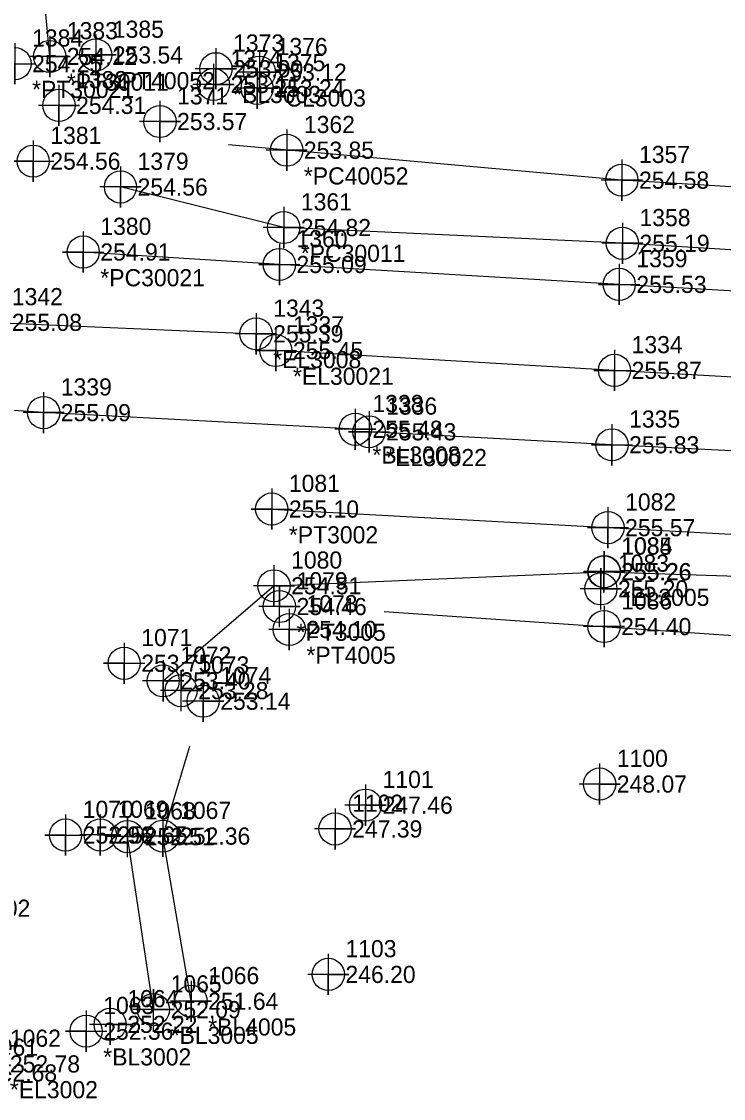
# Model space of a CAD drawing. Extents: x 2130962 to 2131465, y 643052 to 644206.
# Drawn here: x 2131260.2 to 2131362.5, y 643070.6 to 643227.7 of the extents above; entities that cross this region are included whole.
import ezdxf

# ---------------------------------------------------------------- set-up
doc = ezdxf.new("R2010")
doc.units = 0
for name, color, linetype in [('Exist DTM Breakline', 7, 'Continuous'), ('Exist DTM Breakline Cogo Comment', 7, 'Continuous'), ('Exist DTM Breakline Cogo Elevation', 7, 'Continuous'), ('Exist DTM Breakline Cogo Number', 7, 'Continuous'), ('Exist DTM Breakline Cogo Point CELL', 7, 'Continuous'), ('Exist DTM Crownline', 7, 'Continuous'), ('Exist DTM Crownline Cogo Comment', 7, 'Continuous'), ('Exist DTM Crownline Cogo Elevation', 7, 'Continuous'), ('Exist DTM Crownline Cogo Number', 7, 'Continuous'), ('Exist DTM Crownline Cogo Point CELL', 7, 'Continuous'), ('Exist DTM Regular Point CELL', 7, 'Continuous'), ('Exist DTM Regular Point Cogo Elevation', 7, 'Continuous'), ('Exist DTM Regular Point Cogo Number', 7, 'Continuous'), ('Exist Roads EOP', 7, 'Continuous'), ('Exist Roads EOP Cogo Comment', 7, 'Continuous'), ('Exist Roads EOP Cogo Elevation', 7, 'Continuous'), ('Exist Roads EOP Cogo Number', 7, 'Continuous'), ('Exist Roads EOP Cogo Point CELL', 7, 'Continuous'), ('Exist Roads EOP Other Cogo Comment', 7, 'Continuous'), ('Exist Roads EOP Other Cogo Elevation', 7, 'Continuous'), ('Exist Roads EOP Other Cogo Number', 7, 'Continuous'), ('Exist Roads EOP Other Cogo Point CELL', 7, 'Continuous'), ('Exist Roads EOT', 7, 'Continuous'), ('Exist Roads EOT Cogo Comment', 7, 'Continuous'), ('Exist Roads EOT Cogo Elevation', 7, 'Continuous'), ('Exist Roads EOT Cogo Number', 7, 'Continuous'), ('Exist Roads EOT Cogo Point CELL', 7, 'Continuous'), ('Exist Roads Soil', 7, 'Continuous'), ('Exist Roads Soil Cogo Comment', 7, 'Continuous'), ('Exist Roads Soil Cogo Elevation', 7, 'Continuous'), ('Exist Roads Soil Cogo Number', 7, 'Continuous'), ('Exist Roads Soil Cogo Point CELL', 7, 'Continuous')]:
    doc.layers.add(name, color=color, linetype=linetype)

msp = doc.modelspace()

# ---------------------------------------------------------------- linework, layer by layer
at = {"layer": 'Exist DTM Breakline'}
msp.add_line((2131313.0171, 643141.6555), (2131395.8335, 643135.9257), dxfattribs=at)
for points in [[(2131447.7276, 643199.0466), (2131397.0228, 643201.4878), (2131347.6587, 643204.5248), (2131290.3074, 643209.6518)], [(2131284.8719, 643084.8081), (2131280.7793, 643108.8884), (2131284.6857, 643122.0133)]]:
    msp.add_lwpolyline(points, dxfattribs=at)
at = {"layer": 'Exist DTM Breakline Cogo Point CELL'}
for points in [[(2131270.9763, 643225.7805), (2131270.9763, 643219.7805), (2131270.9763, 643222.7805), (2131273.9763, 643222.7805), (2131267.9763, 643222.7805)], [(2131280.339, 643216.0688), (2131280.339, 643210.0688), (2131280.339, 643213.0688), (2131283.339, 643213.0688), (2131277.339, 643213.0688)], [(2131298.816, 643211.8912), (2131298.816, 643205.8912), (2131298.816, 643208.8912), (2131301.816, 643208.8912), (2131295.816, 643208.8912)], [(2131347.6587, 643207.5248), (2131347.6587, 643201.5248), (2131347.6587, 643204.5248), (2131350.6587, 643204.5248), (2131344.6587, 643204.5248)], [(2131299.1949, 643142.0122), (2131299.1949, 643136.0122), (2131299.1949, 643139.0122), (2131302.1949, 643139.0122), (2131296.1949, 643139.0122)], [(2131345.0539, 643142.439), (2131345.0539, 643136.439), (2131345.0539, 643139.439), (2131348.0539, 643139.439), (2131342.0539, 643139.439)], [(2131286.6315, 643131.5508), (2131286.6315, 643125.5508), (2131286.6315, 643128.5508), (2131289.6315, 643128.5508), (2131283.6315, 643128.5508)], [(2131280.7793, 643111.8884), (2131280.7793, 643105.8884), (2131280.7793, 643108.8884), (2131283.7793, 643108.8884), (2131277.7793, 643108.8884)], [(2131284.8719, 643087.8081), (2131284.8719, 643081.8081), (2131284.8719, 643084.8081), (2131287.8719, 643084.8081), (2131281.8719, 643084.8081)]]:
    msp.add_lwpolyline(points, dxfattribs=at)
for centre in [(2131270.9763, 643222.7805), (2131280.339, 643213.0688), (2131298.816, 643208.8912), (2131347.6587, 643204.5248), (2131345.0539, 643139.439), (2131299.1949, 643139.0122), (2131286.6315, 643128.5508), (2131280.7793, 643108.8884), (2131284.8719, 643084.8081)]:
    msp.add_circle(centre, 2.344, dxfattribs=at)
at = {"layer": 'Exist DTM Crownline'}
for points in [[(2131228.6932, 643183.6314), (2131256.2577, 643183.7922), (2131294.3471, 643182.1169)], [(2131308.8055, 643168.2032), (2131263.3929, 643170.6252), (2131227.5461, 643173.0169)]]:
    msp.add_lwpolyline(points, dxfattribs=at)
at = {"layer": 'Exist DTM Crownline Cogo Point CELL'}
for points in [[(2131294.3471, 643185.1169), (2131294.3471, 643179.1169), (2131294.3471, 643182.1169), (2131297.3471, 643182.1169), (2131291.3471, 643182.1169)], [(2131263.3929, 643173.6252), (2131263.3929, 643167.6252), (2131263.3929, 643170.6252), (2131266.3929, 643170.6252), (2131260.3929, 643170.6252)], [(2131308.8055, 643171.2032), (2131308.8055, 643165.2032), (2131308.8055, 643168.2032), (2131311.8055, 643168.2032), (2131305.8055, 643168.2032)]]:
    msp.add_lwpolyline(points, dxfattribs=at)
for centre in [(2131294.3471, 643182.1169), (2131263.3929, 643170.6252), (2131308.8055, 643168.2032)]:
    msp.add_circle(centre, 2.344, dxfattribs=at)
at = {"layer": 'Exist DTM Regular Point CELL'}
for points in [[(2131344.4182, 643119.4774), (2131344.4182, 643113.4774), (2131344.4182, 643116.4774), (2131347.4182, 643116.4774), (2131341.4182, 643116.4774)], [(2131310.2902, 643116.4027), (2131310.2902, 643110.4027), (2131310.2902, 643113.4027), (2131313.2902, 643113.4027), (2131307.2902, 643113.4027)], [(2131305.8527, 643112.9315), (2131305.8527, 643106.9315), (2131305.8527, 643109.9315), (2131308.8527, 643109.9315), (2131302.8527, 643109.9315)], [(2131304.8747, 643091.7233), (2131304.8747, 643085.7233), (2131304.8747, 643088.7233), (2131307.8747, 643088.7233), (2131301.8747, 643088.7233)]]:
    msp.add_lwpolyline(points, dxfattribs=at)
for centre in [(2131344.4182, 643116.4774), (2131310.2902, 643113.4027), (2131305.8527, 643109.9315), (2131304.8747, 643088.7233)]:
    msp.add_circle(centre, 2.344, dxfattribs=at)
at = {"layer": 'Exist Roads EOP'}
for points in [[(2131264.2715, 643222.5647), (2131259.8757, 643269.3254), (2131257.0196, 643319.4043), (2131254.2561, 643369.6499), (2131250.0777, 643419.4187), (2131246.1511, 643469.0294), (2131240.8382, 643519.1271), (2131234.3674, 643568.5584), (2131226.3321, 643620.1808), (2131217.0271, 643668.7116), (2131205.6213, 643717.607), (2131192.0578, 643767.2595), (2131177.9714, 643815.0911), (2131162.2913, 643862.9344), (2131145.3604, 643910.8486), (2131126.9113, 643957.2915), (2131112.3691, 643996.1228)], [(2131447.2378, 643189.5276), (2131397.3957, 643192.2966), (2131347.7242, 643195.3218), (2131298.3748, 643197.6139), (2131274.5841, 643203.5275)], [(2131280.8132, 643131.5166), (2131296.9579, 643145.3867), (2131345.0473, 643147.4189), (2131395.7747, 643145.7863), (2131444.2123, 643144.2465)]]:
    msp.add_lwpolyline(points, dxfattribs=at)
at = {"layer": 'Exist Roads EOP Cogo Point CELL'}
for points in [[(2131264.2715, 643225.5647), (2131264.2715, 643219.5647), (2131264.2715, 643222.5647), (2131267.2715, 643222.5647), (2131261.2715, 643222.5647)], [(2131265.6198, 643218.4271), (2131265.6198, 643212.4271), (2131265.6198, 643215.4271), (2131268.6198, 643215.4271), (2131262.6198, 643215.4271)], [(2131274.5841, 643206.5275), (2131274.5841, 643200.5275), (2131274.5841, 643203.5275), (2131277.5841, 643203.5275), (2131271.5841, 643203.5275)], [(2131298.3748, 643200.6139), (2131298.3748, 643194.6139), (2131298.3748, 643197.6139), (2131301.3748, 643197.6139), (2131295.3748, 643197.6139)], [(2131347.7242, 643198.3218), (2131347.7242, 643192.3218), (2131347.7242, 643195.3218), (2131350.7242, 643195.3218), (2131344.7242, 643195.3218)], [(2131345.0473, 643150.4189), (2131345.0473, 643144.4189), (2131345.0473, 643147.4189), (2131348.0473, 643147.4189), (2131342.0473, 643147.4189)], [(2131296.9579, 643148.3867), (2131296.9579, 643142.3867), (2131296.9579, 643145.3867), (2131299.9579, 643145.3867), (2131293.9579, 643145.3867)], [(2131280.8132, 643134.5166), (2131280.8132, 643128.5166), (2131280.8132, 643131.5166), (2131283.8132, 643131.5166), (2131277.8132, 643131.5166)], [(2131271.6455, 643112.0511), (2131271.6455, 643106.0511), (2131271.6455, 643109.0511), (2131274.6455, 643109.0511), (2131268.6455, 643109.0511)], [(2131273.0839, 643084.4429), (2131273.0839, 643078.4429), (2131273.0839, 643081.4429), (2131276.0839, 643081.4429), (2131270.0839, 643081.4429)]]:
    msp.add_lwpolyline(points, dxfattribs=at)
for centre in [(2131264.2715, 643222.5647), (2131265.6198, 643215.4271), (2131274.5841, 643203.5275), (2131298.3748, 643197.6139), (2131347.7242, 643195.3218), (2131345.0473, 643147.4189), (2131296.9579, 643145.3867), (2131280.8132, 643131.5166), (2131271.6455, 643109.0511), (2131273.0839, 643081.4429)]:
    msp.add_circle(centre, 2.344, dxfattribs=at)
at = {"layer": 'Exist Roads EOP Other Cogo Point CELL'}
for points in [[(2131288.4961, 643223.7686), (2131288.4961, 643217.7686), (2131288.4961, 643220.7686), (2131291.4961, 643220.7686), (2131285.4961, 643220.7686)], [(2131294.8401, 643223.2582), (2131294.8401, 643217.2582), (2131294.8401, 643220.2582), (2131297.8401, 643220.2582), (2131291.8401, 643220.2582)], [(2131288.1379, 643221.4835), (2131288.1379, 643215.4835), (2131288.1379, 643218.4835), (2131291.1379, 643218.4835), (2131285.1379, 643218.4835)], [(2131294.5029, 643220.9136), (2131294.5029, 643214.9136), (2131294.5029, 643217.9136), (2131297.5029, 643217.9136), (2131291.5029, 643217.9136)]]:
    msp.add_lwpolyline(points, dxfattribs=at)
for centre in [(2131288.4961, 643220.7686), (2131294.8401, 643220.2582), (2131288.1379, 643218.4835), (2131294.5029, 643217.9136)]:
    msp.add_circle(centre, 2.344, dxfattribs=at)
at = {"layer": 'Exist Roads EOT'}
for points in [[(2131447.0543, 643183.628), (2131397.23, 643186.4537), (2131347.2728, 643189.3277), (2131297.7395, 643192.2318), (2131269.1537, 643194.0491)], [(2131446.3277, 643171.1555), (2131396.6439, 643173.9458), (2131346.5769, 643176.7932), (2131297.2277, 643179.6845)], [(2131445.8347, 643160.7067), (2131396.5039, 643163.4177), (2131346.2151, 643165.9442), (2131310.8065, 643167.8349)], [(2131296.63, 643156.5688), (2131345.6305, 643153.8593), (2131395.87, 643151.1658)]]:
    msp.add_lwpolyline(points, dxfattribs=at)
at = {"layer": 'Exist Roads EOT Cogo Point CELL'}
for points in [[(2131259.2129, 643224.5063), (2131259.2129, 643218.5063), (2131259.2129, 643221.5063), (2131256.2129, 643221.5063), (2131262.2129, 643221.5063)], [(2131261.865, 643210.302), (2131261.865, 643204.302), (2131261.865, 643207.302), (2131258.865, 643207.302), (2131264.865, 643207.302)], [(2131269.1537, 643197.0491), (2131269.1537, 643191.0491), (2131269.1537, 643194.0491), (2131266.1537, 643194.0491), (2131272.1537, 643194.0491)], [(2131297.7395, 643195.2318), (2131297.7395, 643189.2318), (2131297.7395, 643192.2318), (2131294.7395, 643192.2318), (2131300.7395, 643192.2318)], [(2131347.2728, 643192.3277), (2131347.2728, 643186.3277), (2131347.2728, 643189.3277), (2131344.2728, 643189.3277), (2131350.2728, 643189.3277)], [(2131297.2277, 643182.6845), (2131297.2277, 643176.6845), (2131297.2277, 643179.6845), (2131294.2277, 643179.6845), (2131300.2277, 643179.6845)], [(2131346.5769, 643179.7932), (2131346.5769, 643173.7932), (2131346.5769, 643176.7932), (2131343.5769, 643176.7932), (2131349.5769, 643176.7932)], [(2131310.8065, 643170.8349), (2131310.8065, 643164.8349), (2131310.8065, 643167.8349), (2131307.8065, 643167.8349), (2131313.8065, 643167.8349)], [(2131346.2151, 643168.9442), (2131346.2151, 643162.9442), (2131346.2151, 643165.9442), (2131343.2151, 643165.9442), (2131349.2151, 643165.9442)], [(2131296.63, 643159.5688), (2131296.63, 643153.5688), (2131296.63, 643156.5688), (2131293.63, 643156.5688), (2131299.63, 643156.5688)], [(2131345.6305, 643156.8593), (2131345.6305, 643150.8593), (2131345.6305, 643153.8593), (2131342.6305, 643153.8593), (2131348.6305, 643153.8593)], [(2131275.1215, 643137.0881), (2131275.1215, 643131.0881), (2131275.1215, 643134.0881), (2131272.1215, 643134.0881), (2131278.1215, 643134.0881)], [(2131266.5862, 643112.0425), (2131266.5862, 643106.0425), (2131266.5862, 643109.0425), (2131263.5862, 643109.0425), (2131269.5862, 643109.0425)], [(2131269.5812, 643083.4443), (2131269.5812, 643077.4443), (2131269.5812, 643080.4443), (2131266.5812, 643080.4443), (2131272.5812, 643080.4443)]]:
    msp.add_lwpolyline(points, dxfattribs=at)
for centre in [(2131259.2129, 643221.5063), (2131261.865, 643207.302), (2131269.1537, 643194.0491), (2131297.7395, 643192.2318), (2131347.2728, 643189.3277), (2131297.2277, 643179.6845), (2131346.5769, 643176.7932), (2131310.8065, 643167.8349), (2131346.2151, 643165.9442), (2131296.63, 643156.5688), (2131345.6305, 643153.8593), (2131275.1215, 643134.0881), (2131266.5862, 643109.0425), (2131269.5812, 643080.4443)]:
    msp.add_circle(centre, 2.344, dxfattribs=at)
at = {"layer": 'Exist Roads Soil'}
msp.add_lwpolyline([(2131279.3978, 643083.5901), (2131275.6146, 643108.8098)], dxfattribs=at)
at = {"layer": 'Exist Roads Soil Cogo Point CELL'}
for points in [[(2131345.0899, 643144.45), (2131345.0899, 643150.45), (2131345.0899, 643147.45), (2131348.0899, 643147.45), (2131342.0899, 643147.45)], [(2131344.5951, 643141.934), (2131344.5951, 643147.934), (2131344.5951, 643144.934), (2131347.5951, 643144.934), (2131341.5951, 643144.934)], [(2131297.7505, 643139.3596), (2131297.7505, 643145.3596), (2131297.7505, 643142.3596), (2131300.7505, 643142.3596), (2131294.7505, 643142.3596)], [(2131283.4229, 643127.0933), (2131283.4229, 643133.0933), (2131283.4229, 643130.0933), (2131286.4229, 643130.0933), (2131280.4229, 643130.0933)], [(2131275.6146, 643105.8098), (2131275.6146, 643111.8098), (2131275.6146, 643108.8098), (2131278.6146, 643108.8098), (2131272.6146, 643108.8098)], [(2131279.3978, 643080.5901), (2131279.3978, 643086.5901), (2131279.3978, 643083.5901), (2131282.3978, 643083.5901), (2131276.3978, 643083.5901)]]:
    msp.add_lwpolyline(points, dxfattribs=at)
for centre in [(2131345.0899, 643147.45), (2131344.5951, 643144.934), (2131297.7505, 643142.3596), (2131283.4229, 643130.0933), (2131275.6146, 643108.8098), (2131279.3978, 643083.5901)]:
    msp.add_circle(centre, 2.344, dxfattribs=at)

# ---------------------------------------------------------------- texts
at = {"layer": 'Exist DTM Breakline Cogo Comment'}
for s, p in [('*PT40052', (2131273.4763, 643217.7805)), ('*PC40052', (2131301.316, 643203.8912)), ('*PT4005', (2131301.6949, 643134.0122)), ('*BL4005', (2131287.3719, 643079.8081))]:
    msp.add_text(s, height=2.5, dxfattribs=at).set_placement(p)
at = {"layer": 'Exist DTM Breakline Cogo Elevation'}
for s, p in [('253.54', (2131273.4763, 643221.5305)), ('253.57', (2131282.839, 643211.8188)), ('253.85', (2131301.316, 643207.6412)), ('254.58', (2131350.1587, 643203.2748)), ('254.10', (2131301.6949, 643137.7622)), ('254.40', (2131347.5539, 643138.189)), ('253.14', (2131289.1315, 643127.3008)), ('252.36', (2131283.2793, 643107.6384)), ('251.64', (2131287.3719, 643083.5581))]:
    msp.add_text(s, height=2.5, dxfattribs=at).set_placement(p)
at = {"layer": 'Exist DTM Breakline Cogo Number'}
for s, p in [('1385', (2131273.4763, 643225.2805)), ('1371', (2131282.839, 643215.5688)), ('1362', (2131301.316, 643211.3912)), ('1357', (2131350.1587, 643207.0248)), ('1078', (2131301.6949, 643141.5122)), ('1086', (2131347.5539, 643141.939)), ('1074', (2131289.1315, 643131.0508)), ('1067', (2131283.2793, 643111.3884)), ('1066', (2131287.3719, 643087.3081))]:
    msp.add_text(s, height=2.5, dxfattribs=at).set_placement(p)
at = {"layer": 'Exist DTM Crownline Cogo Comment'}
for s, p in [('*EL3008', (2131296.8471, 643177.1169)), ('*BL3008', (2131311.3055, 643163.2032))]:
    msp.add_text(s, height=2.5, dxfattribs=at).set_placement(p)
at = {"layer": 'Exist DTM Crownline Cogo Elevation'}
for s, p in [('255.08', (2131258.7577, 643182.5422)), ('255.39', (2131296.8471, 643180.8669)), ('255.09', (2131265.8929, 643169.3752)), ('255.48', (2131311.3055, 643166.9532))]:
    msp.add_text(s, height=2.5, dxfattribs=at).set_placement(p)
at = {"layer": 'Exist DTM Crownline Cogo Number'}
for s, p in [('1342', (2131258.7577, 643186.2922)), ('1343', (2131296.8471, 643184.6169)), ('1339', (2131265.8929, 643173.1252)), ('1338', (2131311.3055, 643170.7032))]:
    msp.add_text(s, height=2.5, dxfattribs=at).set_placement(p)
at = {"layer": 'Exist DTM Regular Point Cogo Elevation'}
for s, p in [('248.07', (2131346.9182, 643115.2274)), ('247.46', (2131312.7902, 643112.1527)), ('247.39', (2131308.3527, 643108.6815)), ('246.20', (2131307.3747, 643087.4733))]:
    msp.add_text(s, height=2.5, dxfattribs=at).set_placement(p)
at = {"layer": 'Exist DTM Regular Point Cogo Number'}
for s, p in [('1100', (2131346.9182, 643118.9774)), ('1101', (2131312.7902, 643115.9027)), ('1102', (2131308.3527, 643112.4315)), ('1103', (2131307.3747, 643091.2233))]:
    msp.add_text(s, height=2.5, dxfattribs=at).set_placement(p)
at = {"layer": 'Exist Roads EOP Cogo Comment'}
for s, p in [('*PT30011', (2131266.7715, 643217.5647)), ('*PC30011', (2131300.8748, 643192.6139))]:
    msp.add_text(s, height=2.5, dxfattribs=at).set_placement(p)
at = {"layer": 'Exist Roads EOP Cogo Elevation'}
for s, p in [('254.12', (2131266.7715, 643221.3147)), ('254.31', (2131268.1198, 643214.1771)), ('254.56', (2131277.0841, 643202.2775)), ('254.82', (2131300.8748, 643196.3639)), ('255.19', (2131350.2242, 643194.0718)), ('255.26', (2131347.5473, 643146.1689)), ('254.51', (2131299.4579, 643144.1367)), ('253.40', (2131283.3132, 643130.2666)), ('252.65', (2131274.1455, 643107.8011)), ('252.22', (2131275.5839, 643080.1929)), ('252.68', (2131255.1325, 643073.1047))]:
    msp.add_text(s, height=2.5, dxfattribs=at).set_placement(p)
at = {"layer": 'Exist Roads EOP Cogo Number'}
for s, p in [('1383', (2131266.7715, 643225.0647)), ('1382', (2131268.1198, 643217.9271)), ('1379', (2131277.0841, 643206.0275)), ('1361', (2131300.8748, 643200.1139)), ('1358', (2131350.2242, 643197.8218)), ('1085', (2131347.5473, 643149.9189)), ('1080', (2131299.4579, 643147.8867)), ('1072', (2131283.3132, 643134.0166)), ('1069', (2131274.1455, 643111.5511)), ('1064', (2131275.5839, 643083.9429)), ('1061', (2131255.1325, 643076.8547))]:
    msp.add_text(s, height=2.5, dxfattribs=at).set_placement(p)
at = {"layer": 'Exist Roads EOP Other Cogo Comment'}
for s, p in [('*BL3003', (2131290.9961, 643215.7686)), ('*CL3003', (2131297.3401, 643215.2582))]:
    msp.add_text(s, height=2.5, dxfattribs=at).set_placement(p)
at = {"layer": 'Exist Roads EOP Other Cogo Elevation'}
for s, p in [('253.00', (2131290.9961, 643219.5186)), ('253.12', (2131297.3401, 643219.0082)), ('253.11', (2131290.6379, 643217.2335)), ('253.24', (2131297.0029, 643216.6636))]:
    msp.add_text(s, height=2.5, dxfattribs=at).set_placement(p)
at = {"layer": 'Exist Roads EOP Other Cogo Number'}
for s, p in [('1373', (2131290.9961, 643223.2686)), ('1376', (2131297.3401, 643222.7582)), ('1374', (2131290.6379, 643220.9835)), ('1375', (2131297.0029, 643220.4136))]:
    msp.add_text(s, height=2.5, dxfattribs=at).set_placement(p)
at = {"layer": 'Exist Roads EOT Cogo Comment'}
for s, p in [('*PT30021', (2131261.7129, 643216.5063)), ('*PC30021', (2131271.6537, 643189.0491)), ('*EL30021', (2131299.7277, 643174.6845)), ('*EL30022', (2131313.3065, 643162.8349)), ('*PT3002', (2131299.13, 643151.5688)), ('*PT3002', (2131248.4361, 643097.1206)), ('*BL3002', (2131272.0812, 643075.4443)), ('*EL3002', (2131258.4743, 643070.6707))]:
    msp.add_text(s, height=2.5, dxfattribs=at).set_placement(p)
at = {"layer": 'Exist Roads EOT Cogo Elevation'}
for s, p in [('254.25', (2131261.7129, 643220.2563)), ('254.56', (2131264.365, 643206.052)), ('254.91', (2131271.6537, 643192.7991)), ('255.09', (2131300.2395, 643190.9818)), ('255.53', (2131349.7728, 643188.0777)), ('255.45', (2131299.7277, 643178.4345)), ('255.87', (2131349.0769, 643175.5432)), ('255.43', (2131313.3065, 643166.5849)), ('255.83', (2131348.7151, 643164.6942)), ('255.10', (2131299.13, 643155.3188)), ('255.57', (2131348.1305, 643152.6093)), ('253.75', (2131277.6215, 643132.8381)), ('252.96', (2131269.0862, 643107.7925)), ('252.36', (2131272.0812, 643079.1943)), ('252.78', (2131258.4743, 643074.4207))]:
    msp.add_text(s, height=2.5, dxfattribs=at).set_placement(p)
at = {"layer": 'Exist Roads EOT Cogo Number'}
for s, p in [('1384', (2131261.7129, 643224.0063)), ('1381', (2131264.365, 643209.802)), ('1380', (2131271.6537, 643196.5491)), ('1360', (2131300.2395, 643194.7318)), ('1359', (2131349.7728, 643191.8277)), ('1337', (2131299.7277, 643182.1845)), ('1334', (2131349.0769, 643179.2932)), ('1336', (2131313.3065, 643170.3349)), ('1335', (2131348.7151, 643168.4442)), ('1081', (2131299.13, 643159.0688)), ('1082', (2131348.1305, 643156.3593)), ('1071', (2131277.6215, 643136.5881)), ('1070', (2131269.0862, 643111.5425)), ('1063', (2131272.0812, 643082.9443)), ('1062', (2131258.4743, 643078.1707))]:
    msp.add_text(s, height=2.5, dxfattribs=at).set_placement(p)
at = {"layer": 'Exist Roads Soil Cogo Comment'}
for s, p in [('*EL3005', (2131347.5899, 643142.45)), ('*PT3005', (2131300.2505, 643137.3596)), ('*BL3005', (2131281.8978, 643078.5901))]:
    msp.add_text(s, height=2.5, dxfattribs=at).set_placement(p)
at = {"layer": 'Exist Roads Soil Cogo Elevation'}
for s, p in [('255.26', (2131347.5899, 643146.2)), ('255.20', (2131347.0951, 643143.684)), ('254.46', (2131300.2505, 643141.1096)), ('253.28', (2131285.9229, 643128.8433)), ('252.51', (2131278.1146, 643107.5598)), ('252.09', (2131281.8978, 643082.3401))]:
    msp.add_text(s, height=2.5, dxfattribs=at).set_placement(p)
at = {"layer": 'Exist Roads Soil Cogo Number'}
for s, p in [('1084', (2131347.5899, 643149.95)), ('1083', (2131347.0951, 643147.434)), ('1079', (2131300.2505, 643144.8596)), ('1073', (2131285.9229, 643132.5933)), ('1068', (2131278.1146, 643111.3098)), ('1065', (2131281.8978, 643086.0901))]:
    msp.add_text(s, height=2.5, dxfattribs=at).set_placement(p)

doc.saveas('drawing.dxf')
